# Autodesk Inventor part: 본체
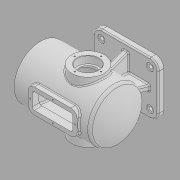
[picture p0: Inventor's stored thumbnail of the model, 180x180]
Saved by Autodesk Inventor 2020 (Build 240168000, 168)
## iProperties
Created: 2021-11
Part Number: 본체
Material: 일반
Document SubType Name: Modeling
Designer: Administrator
Density: 1 g/cm^3
Appearance: 기본값
Mass: 1357.46 g
Surface Area: 2500.17 cm^2
Volume: 1357.46 cm^3
Author: Administrator
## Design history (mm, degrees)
sketch "스케치1"
  geometry: L1 (-80, -65)-(80, -65); L2 (80, -65)-(80, 65); L3 (80, 65)-(-80, 65); L4 (-80, 65)-(-80, -65); L5 (-80, -65)-(80, 65); L6 (80, -65)-(-80, 65); 1 further point
  constraints: 12 end point, 2 midpoint, 2 parallel, 1 horizontal, 1 perpendicular
  dimensions: "d0" = 160 distance of L3.end L2.end; "d1" = 130 distance of L2.end L1.end
extrude "돌출1" new body sketch "스케치1" distance "d2" = 14; taper "d3" = 0 deg
sketch "스케치2"
  geometry: L1 (110, 179)-(-75.993, 179); L2 (-100, 114)-(110, 114); L3 (110, 114)-(110, 179); L4 (80, 0)-(-80, 0) reference; L5 (-75.993, 179)-(-75.993, 49); A1 r 100 centre (0, 114) between (-75.993, 179) and (-75.993, 49); 4 further points
  constraints: 8 end point, 3 point on circle, 2 midpoint, 2 vertical alignment, 1 centre point, 1 horizontal, 1 parallel, 1 point on line, 1 vertical
  dimensions: "d4" = 114 distance between parallel lines of L4 L2; "d6" = 130 diameter of L1 L2; "d61" = 130 distance of L1.end L5.end; "d62" = 100 radius of A1; "d63" = 210 distance from line of L2.start L3; "d65" = 65 distance of L2.end L1.start
revolve "회전1" sketch "스케치2" stored, may be unused: angle "d7" = 90 deg
sketch "스케치3"
  geometry: C1 r 65 at (0, 0) reference; C2 r 47.5 at (0, 0); 1 further point
  constraints: 1 centre point, 1 coincident
  dimensions: "d8" = 95 diameter of C2
extrude "돌출2" join sketch "스케치3" distance "d9" = 10; taper "d10" = 0 deg
node "작업 평면4"
sketch "스케치5"
  geometry: L1 (-70, 30)-(50, 30); L2 (50, 30)-(50, -30); L3 (50, -30)-(-70, -30); L4 (-70, -30)-(-70, 30); L5 (-120, 47.5)-(-120, -47.5) reference; L6 (80, 65)-(-80, 65) reference; L7 (-120, 0)-(84.938, 0); L8 (-80, -65)-(80, -65) reference; 3 further points
  constraints: 10 end point, 3 midpoint, 2 horizontal, 2 horizontal alignment, 2 parallel, 1 perpendicular, 1 vertical alignment
  dimensions: "d17" = 50 distance between parallel lines of L4 L5; "d18" = 120 distance of L1.start L1.end; "d19" = 60 distance of L3.end L1.start
extrude "돌출3" join sketch "스케치5" stored distance "d21" = 10; taper "d22" = 0 deg
sketch "스케치7"
  geometry: L1 (-7, 7)-(7, 7); L2 (7, 7)-(7, -7); L3 (7, -7)-(-7, -7); L4 (-7, -7)-(-7, 7); L5 (-7, 7)-(7, -7); L6 (7, 7)-(-7, -7); 1 further point
  constraints: 12 end point, 2 midpoint, 2 parallel, 1 horizontal, 1 perpendicular
  dimensions: "d27" = 14 distance of L2.end L3.end; "d28" = 14 distance of L1.end L2.end
extrude "돌출5" join sketch "스케치7" stored distance "d29" = 14; taper "d30" = 0 deg
sketch "스케치8"
  geometry: L1 (-50, 179)-(-50, 184) reference; L2 (-50, 184)-(70, 184) reference; L3 (70, 184)-(70, 179) reference; L4 (7, 14)-(80, 14) reference; L5 (80, 14)-(80, 0) reference; L6 (80, 0)-(-80, 0) reference; L7 (-80, 0)-(-80, 14) reference; L8 (-80, 14)-(-7, 14) reference; L9 (49.633, 42.484)-(60, 14); L10 (-50.289, 40.681)-(-60, 14); L11 (0, 0)-(0, 75.238); L12 (-75.993, 179)-(-50, 179) reference; L13 (70, 179)-(110, 179) reference; L14 (110, 179)-(110, 161.5) reference; L15 (110, 161.5)-(120, 161.5) reference; L16 (120, 161.5)-(120, 66.5) reference; L17 (120, 66.5)-(110, 66.5) reference; L18 (110, 66.5)-(110, 49) reference; L19 (110, 49)-(7, 49) reference; L20 (7, 49)-(7, 14) reference; L21 (-7, 14)-(-7, 49) reference; L22 (-7, 49)-(-75.993, 49) reference; A1 r 100 centre (0, 114) between (-75.993, 179) and (-75.993, 49) reference
  constraints: 6 end point, 2 point on line, 1 vertical, 1 other
  dimensions: "d31" = 110 deg angle of L4 L9; "d69" = 120 distance of L10.end L9.end (derived)
  node "절단 모서리 투영1"
feature "리브1" dims "d33" = 1, "d34" = 14, "d35" = 0, "d36" = 0, "d37" = 1, "d38" = 1
feature "리브2" dims "d39" = 1, "d40" = 14, "d41" = 0, "d42" = 0, "d43" = 1, "d44" = 1
sketch "스케치9"
  geometry: L1 (-30, 184)-(30, 184) reference; L2 (30, 184)-(30, 171.663) reference; L3 (7, 14)-(65, 14) reference; L4 (65, 14)-(65, 0) reference; L5 (65, 0)-(-65, 0) reference; L6 (-65, 0)-(-65, 14) reference; L7 (-65, 14)-(-7, 14) reference; L8 (-30, 171.663)-(-30, 184) reference; L9 (39.871, 41.829)-(50, 14); L10 (-39.864, 41.849)-(-50, 14); L11 (0, 0)-(0, 114); L12 (7, 49.378)-(7, 14) reference; L13 (-7, 14)-(-7, 49.378) reference; A1 r 65 centre (0, 114) between (7, 49.378) and (30, 171.663) reference; A2 r 65 centre (0, 114) between (-30, 171.663) and (-7, 49.378) reference
  constraints: 6 end point, 2 point on line, 1 vertical, 1 other
  dimensions: "d45" = 110 deg angle of L7 L10; "d46" = 100 distance of L10.end L9.end
  node "절단 모서리 투영2"
feature "리브3" dims "d47" = 1, "d48" = 14, "d49" = 0, "d50" = 0, "d51" = 1, "d52" = 1
feature "리브4" dims "d53" = 1, "d54" = 14, "d55" = 0, "d56" = 0, "d57" = 1, "d58" = 1
sketch "스케치12"
  geometry: L1 (120, 66.5)-(110, 66.5) reference; L2 (110, 66.5)-(110, 49) reference; L3 (110, 49)-(47.261, 49) reference; L4 (47.261, 49)-(60, 14) reference; L5 (60, 14)-(80, 14) reference; L6 (80, 14)-(80, 0) reference; L7 (80, 0)-(-80, 0) reference; L8 (-80, 0)-(-80, 14) reference; L9 (-80, 14)-(-60, 14) reference; L10 (-60, 14)-(-47.261, 49) reference; L11 (-47.261, 49)-(-75.993, 49) reference; L12 (-75.993, 179)-(-50, 179) reference; L13 (-50, 179)-(-50, 184) reference; L14 (-50, 184)-(70, 184) reference; L15 (70, 184)-(70, 179) reference; L16 (70, 179)-(110, 179) reference; L17 (110, 179)-(110, 161.5) reference; L18 (110, 161.5)-(120, 161.5) reference; L19 (120, 161.5)-(120, 66.5) reference; L20 (120, 146.5)-(95, 146.5); L21 (95, 146.5)-(95, 169); L22 (120, 114)-(-100, 114); L23 (-71.239, 59)-(-32.98, 59); L24 (-32.98, 59)-(-50.814, 10); L25 (-50.814, 10)-(50.814, 10); L26 (50.814, 10)-(32.98, 59); L27 (32.98, 59)-(100, 59); L28 (100, 59)-(100, 76.5); L29 (100, 76.5)-(110, 76.5); L30 (110, 76.5)-(110, 151.5); L31 (110, 151.5)-(100, 151.5); L32 (100, 151.5)-(100, 169); L33 (100, 169)-(60, 169); L34 (60, 169)-(60, 174); L35 (60, 174)-(-40, 174); L36 (-40, 174)-(-40, 169); L37 (-40, 169)-(-71.239, 169); L38 (95, 169)-(-71.239, 169); L39 (120, 146.5)-(120, 114); A1 r 100 centre (0, 114) between (-75.993, 179) and (-75.993, 49) reference; A2 r 90 centre (0, 114) between (-71.239, 169) and (-71.239, 59); A3 r 90 centre (0, 114) between (-71.239, 169) and (-90, 114); 2 further points
  constraints: 40 end point, 6 point on circle, 2 centre point, 2 collinear, 2 concentric, 2 perpendicular, 1 midpoint, 1 point on line, 15 other
  dimensions: "d71" = 25 distance of L20.start L20.end; "d72" = 65 diameter of L20 L22; "d74" = 10 radial gap between concentric circles of A1 A2
revolve "회전4" sketch "스케치12" stored, may be unused: angle "d75" = 90 deg
sketch "스케치13"
  geometry: L1 (-70, -30)-(50, -30) reference; L2 (50, -30)-(50, 30) reference; L3 (50, 30)-(-70, 30) reference; L4 (-70, 30)-(-70, -30) reference; L5 (-60, 20)-(40, 20); L6 (40, 20)-(40, -20); L7 (40, -20)-(-60, -20); L8 (-60, -20)-(-60, 20)
  constraints: 8 end point, 3 other
  dimensions: "d76" = 10 distance between parallel lines of L3 L5
extrude "돌출6" cut sketch "스케치13" stored distance "d77" = 14; taper "d78" = 0 deg
sketch "스케치16" dims "d85" = 80
  geometry: L1 (0, 0)-(40, 0); C1 r 32.5 at (0, 0) reference; C2 r 47.5 at (0, 0) reference; 2 further points
  constraints: 2 coincident, 2 end point, 1 horizontal, 1 horizontal alignment, 2 other
hole "구멍1" sketch "스케치16" at (40, 0) diameter "d86" = 3.242; stored, may be unused: countersink angle "d90" = 90 deg, drill point angle "d92" = 118 deg; dims "d87" = 11, "d88" = 4, "d89" = 2, "d91" = 13
node "작업 평면5"
sketch "스케치19"
  geometry: L1 (40, 75)-(0, 75); L2 (0, 75)-(0, -75); L3 (0, -75)-(40, -75); L4 (40, -75)-(40, 75); C1 r 65 at (0, 0) reference; 2 further points
  constraints: 8 end point, 2 parallel, 1 coincident, 1 horizontal, 1 midpoint, 1 perpendicular
  dimensions: "d115" = 150 distance of L3.end L1.start; "d116" = 80 diameter of L4 L2
revolve "회전5" sketch "스케치19" stored, may be unused: angle "d117" = 90 deg
sketch "스케치20"
  geometry: C1 r 40 at (0, 0) reference; C2 r 26 at (0, 0); C3 r 21 at (0, 0); 1 further point
  constraints: 2 centre point, 2 coincident
  dimensions: "d118" = 52 diameter of C2; "d119" = 42 diameter of C3
  node "투영된 루프9"
extrude "돌출9" cut sketch "스케치20" distance "d120" = 18; taper "d121" = 0 deg
extrude "돌출10" cut sketch "스케치20" stored distance "d122" = 18; taper "d123" = 0 deg
sketch "스케치22"
  geometry: L1 (50, 162.235)-(-60, 162.235); L2 (-60, 162.235)-(-60, 69.378); L3 (-60, 69.378)-(50, 69.378); L4 (50, 69.378)-(50, 162.235); L5 (-40, 165.235)-(60, 165.235) reference; L6 (-47.123, 49.378)-(-7, 49.378) reference; L7 (120, 146.5)-(120, 81.5) reference; 3 further points
  constraints: 8 end point, 2 midpoint, 2 parallel, 1 horizontal, 1 horizontal alignment, 1 perpendicular
  dimensions: "d124" = 3 distance between parallel lines of L5 L1; "d125" = 20 distance between parallel lines of L6 L3; "d126" = 110 distance of L1.start L1.end; "d127" = 70 distance between parallel lines of L4 L7
extrude "돌출11" cut sketch "스케치22" stored distance "d128" = 200; taper "d129" = 0 deg; dims "d17" = 50, "d18" = 120, "d19" = 60
extrude "돌출12" cut sketch "스케치22" stored distance "d130" = 200; taper "d131" = 0 deg; dims "d17" = 50, "d18" = 120, "d19" = 60
sketch "스케치23"
  geometry: L1 (-65, 25)-(45, 25); L2 (45, 25)-(45, -25); L3 (45, -25)-(-65, -25); L4 (-65, -25)-(-65, 25); L5 (-10, 25)-(-10, -25); L6 (-33, 75)-(47, 75) reference; L7 (7, 75)-(7, 90.631); L8 (50, -30)-(50, 30) reference; 6 further points
  constraints: 12 end point, 6 midpoint, 3 coincident, 2 parallel, 1 horizontal, 1 horizontal alignment, 1 perpendicular, 1 vertical
  dimensions: "d133" = 50 distance of L3.end L1.start; "d135" = 55 distance between parallel lines of L5 L4; "d136" = 17 distance between parallel lines of L5 L7
hole "구멍3" sketch "스케치23" at (-10, 25), (-10, -25), (-65, 0), (45, 0) diameter "d137" = 3.242; stored, may be unused: countersink angle "d141" = 90 deg, drill point angle "d143" = 118 deg; dims "d138" = 11, "d139" = 4, "d140" = 2, "d142" = 13
sketch "스케치24" dims "d144" = 65
  geometry: L1 (0, 0)-(0, 32.5); C1 r 40 at (0, 0) reference; 2 further points
  constraints: 2 coincident, 2 end point, 1 vertical, 1 vertical alignment, 2 other
hole "구멍4" sketch "스케치24" at (0, 32.5) diameter "d145" = 3.242; stored, may be unused: countersink angle "d149" = 90 deg, drill point angle "d151" = 118 deg; dims "d146" = 9, "d147" = 4, "d148" = 2, "d150" = 11
sketch "스케치25"
  geometry: L1 (63.408, 7.402)-(96.592, 7.402); L2 (96.592, 7.402)-(96.592, 2.598); L3 (96.592, 2.598)-(63.408, 2.598); L4 (63.408, 2.598)-(63.408, 7.402); L5 (63.408, 2.598)-(96.592, 7.402); L6 (0, 0)-(160, 0) reference; 3 further points
  constraints: 2 end point, 2 midpoint, 1 vertical alignment, 2 other
  dimensions: "d155" = 5 distance of point (80, 0) point (80, 5)
feature "엠보싱1" sketch "스케치25" dims "d156" = 0.5, "d157" = 0
fillet "모깎기1" dims "d158" = 15
fillet "모깎기2" dims "d159" = 3
fillet "모깎기3" dims "d160" = 3
fillet "모깎기4" dims "d161" = 10
fillet "모깎기5" dims "d162" = 20
sketch "스케치27"
  geometry: A1 r 20 centre (60, -45) between (60, -65) and (80, -45) reference; A2 r 20 centre (-60, -45) between (-80, -45) and (-60, -65) reference; A3 r 20 centre (-60, 45) between (-60, 65) and (-80, 45) reference; A4 r 20 centre (60, 45) between (80, 45) and (60, 65) reference; 5 further points
  constraints: 4 coincident
hole "구멍5" sketch "스케치27" at (60, -45), (-60, -45), (-60, 45), (60, 45) diameter "d163" = 9; stored, may be unused: countersink angle "d167" = 90 deg, drill point angle "d169" = 118 deg; dims "d164" = 9, "d165" = 18, "d166" = 2, "d168" = 11
fillet "모깎기6" dims "d170" = 3
chamfer "모따기1" distance "d171" = 1; stored, may be unused: second distance "d172" = 2, angle "d173" = 45 deg
fillet "모깎기7" dims "d174" = 3
fillet "모깎기8" dims "d175" = 5
node "솔리드1"
pattern_circular "원형 패턴1" dims angle "d94" = 360 deg
mirror "미러3"
pattern_circular "원형 패턴3" dims angle "d153" = 360 deg
mirror "미러4"
node "투영된 루프1"
node "투영된 루프6"
node "투영된 루프8"
node "절단 모서리 투영3"
feature "A9D066F2-1C7D-4E18-AEED-F7BC21143FA4" dims "d163" = 9, "d164" = 9, "d165" = 18, "d166" = 2, "d167" = 90 deg, "d168" = 11, "d169" = 118 deg
other parameters: "d114" = -127
